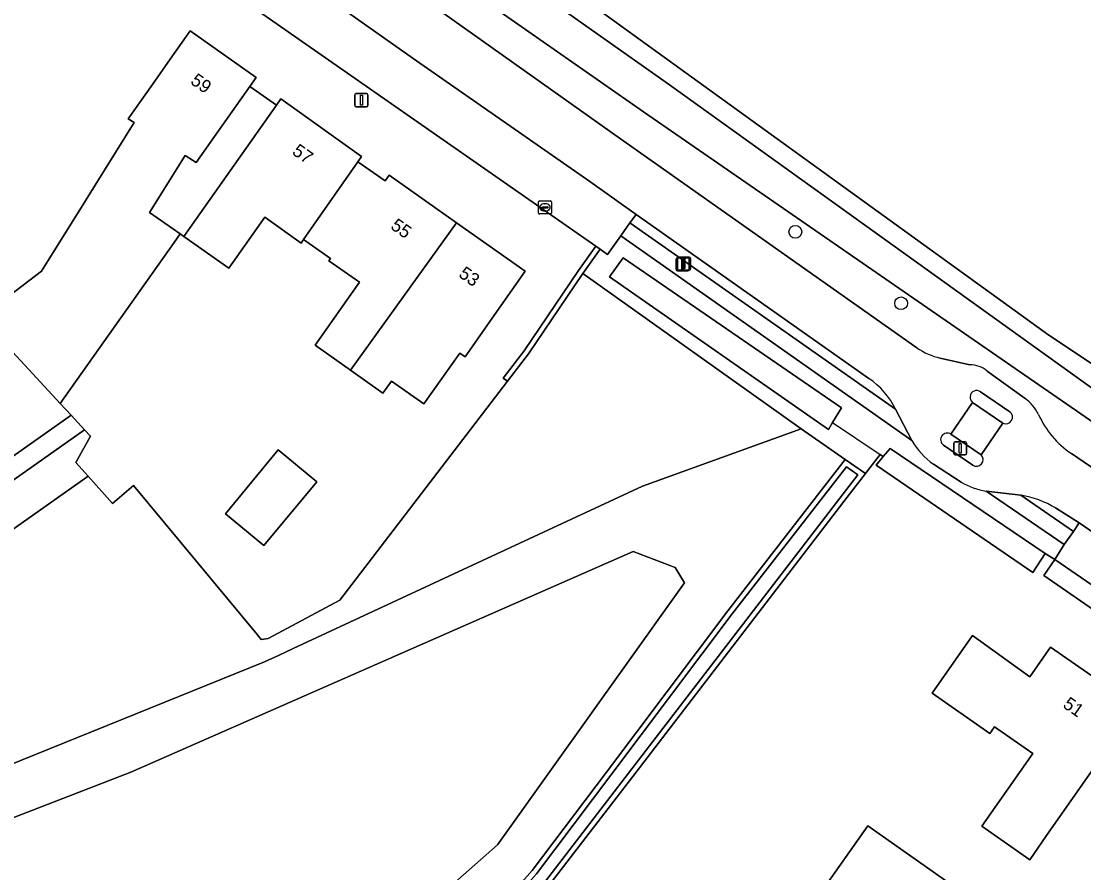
# Model space of a CAD drawing. Extents: x 163859 to 164644, y 379566 to 382155.
# Drawn here: x 164243.8 to 164325.1, y 381742.3 to 381807.4 of the extents above; entities that cross this region are included whole.
import ezdxf

# ---------------------------------------------------------------- set-up
doc = ezdxf.new("R2010")
doc.units = 0
for name, color, linetype in [('IMGEO_Boom', 7, 'Continuous'), ('IMGEO_Duiker', 7, 'Continuous'), ('IMGEO_Erf', 7, 'Continuous'), ('IMGEO_Fietspad_open', 7, 'Continuous'), ('IMGEO_Grasland_agrarisch', 7, 'Continuous'), ('IMGEO_Grasland_overig', 7, 'Continuous'), ('IMGEO_Groenvoorziening', 7, 'Continuous'), ('IMGEO_Haag', 7, 'Continuous'), ('IMGEO_Hek', 7, 'Continuous'), ('IMGEO_Kolk', 7, 'Continuous'), ('IMGEO_Lichtmast', 7, 'Continuous'), ('IMGEO_Loofbos', 7, 'Continuous'), ('IMGEO_Oever', 7, 'Continuous'), ('IMGEO_Pand', 7, 'Continuous'), ('IMGEO_Pand_nummerreeks', 7, 'Continuous'), ('IMGEO_Parkeervlak_open', 7, 'Continuous'), ('IMGEO_Rijbaan_lokaal_gesloten', 7, 'Continuous'), ('IMGEO_Rijbaan_lokaal_open', 7, 'Continuous'), ('IMGEO_Voetpad_onverhard', 7, 'Continuous'), ('IMGEO_Voetpad_open', 7, 'Continuous'), ('IMGEO_Waterloop', 7, 'Continuous')]:
    doc.layers.add(name, color=color, linetype=linetype)

msp = doc.modelspace()

# ---------------------------------------------------------------- linework, layer by layer
at = {"layer": 'IMGEO_Boom'}
for centre in [(164303.037, 381791.326), (164311.134, 381785.861)]:
    msp.add_circle(centre, 0.489, dxfattribs=at)
at = {"layer": 'IMGEO_Duiker'}
msp.add_lwpolyline([(164305.887, 381776.735), (164309.527, 381774.292)], dxfattribs=at)
at = {"layer": 'IMGEO_Erf'}
for points in [[(164232.439, 381822.106), (164231.909, 381821.33), (164235.808, 381818.657), (164230.696, 381811.217), (164225.107, 381816.082), (164225.837, 381817.086), (164221.471, 381820.037), (164221.61, 381820.246), (164220.683, 381820.865), (164219.83, 381819.623), (164212.364, 381823.54), (164205.955, 381814.209), (164235.043, 381794.138), (164235.285, 381793.932), (164235.601, 381793.483), (164234.237, 381791.715), (164240.69, 381784.76), (164245.37, 381788.308), (164248.754, 381793.758), (164252.441, 381799.696), (164251.999, 381799.981), (164253.852, 381802.608)], [(164253.852, 381802.608), (164255.207, 381804.528), (164256.734, 381806.693), (164261.781, 381803.132), (164261.3, 381802.45), (164263.334, 381801.016), (164263.671, 381801.494), (164269.847, 381797.094), (164269.567, 381796.692), (164271.666, 381795.229), (164271.965, 381795.652), (164277.126, 381792.011), (164282.379, 381788.304), (164279.497, 381784.219), (164277.768, 381781.768), (164277.372, 381782.047), (164274.626, 381778.156), (164272.14, 381779.911), (164271.486, 381778.984), (164268.996, 381780.742), (164266.291, 381782.65), (164269.69, 381787.468), (164267.354, 381789.116), (164267.482, 381789.298), (164265.417, 381790.737), (164265.231, 381790.47), (164262.445, 381792.436), (164259.695, 381788.538), (164256.247, 381790.972), (164255.965, 381791.171), (164255.507, 381790.522), (164246.795, 381778.181), (164247.624, 381777.288), (164248.655, 381776.177), (164249.105, 381775.692), (164247.987, 381773.682), (164248.925, 381772.63), (164250.791, 381770.539), (164252.413, 381771.917), (164261.898, 381760.489), (164262.182, 381760.148), (164262.711, 381760.207), (164268.185, 381763.137), (164281.013, 381779.902), (164280.681, 381780.125), (164282.289, 381782.226), (164286.443, 381788.361), (164287.783, 381790.232), (164256.006, 381812.389)], [(164381.892, 381725.724), (164366.579, 381736.251), (164365.238, 381734.407), (164343.09, 381750), (164341.646, 381751.017), (164341.728, 381751.199), (164335.582, 381755.465), (164335.669, 381755.626), (164322.057, 381765.024), (164322.896, 381766.247), (164322.167, 381766.721), (164321.202, 381765.27), (164309.218, 381773.471), (164309.769, 381774.13), (164309.527, 381774.292), (164308.748, 381773.279), (164308.401, 381772.828), (164307.015, 381771.024), (164290.861, 381750), (164280.775, 381736.889), (164280.475, 381736.472), (164297.431, 381715.017), (164336.625, 381665.424)]]:
    msp.add_lwpolyline(points, dxfattribs=at)
for points in [[(164263.476, 381774.646), (164266.428, 381772.203), (164262.385, 381767.319), (164259.434, 381769.762)], [(164320.981, 381743.295), (164317.322, 381745.846), (164321.205, 381751.416), (164318.285, 381753.452), (164317.93, 381752.943), (164313.509, 381756.026), (164316.591, 381760.447), (164320.99, 381757.29), (164322.574, 381759.563), (164329.133, 381754.99), (164325.139, 381749.259), (164322.268, 381745.141)], [(164304.982, 381740.792), (164308.591, 381745.895), (164315.139, 381741.264), (164311.53, 381736.161)]]:
    msp.add_lwpolyline(points, close=True, dxfattribs=at)
at = {"layer": 'IMGEO_Fietspad_open'}
for points in [[(164290.39, 381792.012), (164289.678, 381791.017), (164311.945, 381775.371), (164310.709, 381777.754)], [(164324.32, 381768.391), (164320.292, 381771.18), (164317.646, 381771.484), (164323.62, 381767.407)]]:
    msp.add_lwpolyline(points, close=True, dxfattribs=at)
at = {"layer": 'IMGEO_Grasland_agrarisch'}
msp.add_lwpolyline([(164303.655, 381951.333), (164266.944, 381922.737), (164277.667, 381908.3), (164278.876, 381906.816), (164278.809, 381906.762), (164279.852, 381905.358), (164303.691, 381871.549), (164284.619, 381860.24), (164259.755, 381889.448), (164267.387, 381895.767), (164258.029, 381908.469), (164254.791, 381905.941), (164252.396, 381909.265), (164208.654, 381876.058), (164201.663, 381868.745), (164211.763, 381860.7), (164222.906, 381852.769), (164256.457, 381829.627), (164286.005, 381809.753), (164322.428, 381783.408), (164335.006, 381775.051), (164338.747, 381777.229), (164392.726, 381806.597)], dxfattribs=at)
at = {"layer": 'IMGEO_Grasland_overig'}
msp.add_lwpolyline([(164264.597, 381822.915), (164293.413, 381802.563), (164333.203, 381774.002), (164335.006, 381775.051), (164322.428, 381783.408), (164286.005, 381809.753)], dxfattribs=at)
at = {"layer": 'IMGEO_Groenvoorziening'}
for points in [[(164175.458, 381878.387), (164203.483, 381859.285), (164205.181, 381858.114), (164214.31, 381851.815), (164215.15, 381853.032), (164227.892, 381844.304), (164227.341, 381843.488), (164229.978, 381841.659), (164230.539, 381842.463), (164236.331, 381838.448), (164235.41, 381837.168), (164242.387, 381832.326), (164242.758, 381832.059), (164272.361, 381810.742), (164289.667, 381798.436), (164312.339, 381782.446)], [(164324.169, 381774.363), (164359.822, 381750), (164360.25, 381749.708), (164360.489, 381750.103), (164360.511, 381750.139), (164361.118, 381751.14), (164362.264, 381753.03), (164362.019, 381753.203), (164361.428, 381751.86), (164361.269, 381751.975), (164350.837, 381759.485), (164291.421, 381800.511), (164261.825, 381821.183)], [(164308.664, 381780.116), (164290.856, 381792.662), (164290.39, 381792.012), (164310.709, 381777.754)], [(164311.945, 381775.371), (164289.678, 381791.017), (164288.789, 381789.762), (164288.679, 381789.603), (164288.111, 381790.003), (164286.771, 381788.132), (164303.488, 381776.262), (164306.859, 381773.906), (164308.401, 381772.828), (164308.748, 381773.279), (164309.527, 381774.292), (164309.769, 381774.13), (164310.292, 381774.757), (164322.167, 381766.721), (164322.896, 381766.247), (164323.62, 381767.407), (164317.646, 381771.484)], [(164314.13, 381781.666), (164316.399, 381781.156)], [(164317.71, 381780.678), (164320.628, 381778.579)], [(164319.454, 381777.567), (164317.208, 381779.079)], [(164316.604, 381778.279), (164318.918, 381776.694)], [(164317.251, 381774.26), (164314.948, 381775.851)], [(164314.366, 381775.008), (164316.609, 381773.48)], [(164315.735, 381772.178), (164313.617, 381773.55)], [(164320.292, 381771.18), (164324.32, 381768.391), (164324.768, 381769.068), (164322.955, 381770.199)]]:
    msp.add_lwpolyline(points, dxfattribs=at)
for points in [[(164288.111, 381790.003), (164287.783, 381790.232), (164286.443, 381788.361), (164282.289, 381782.226), (164280.681, 381780.125), (164281.013, 381779.902), (164282.62, 381782.002), (164286.771, 381788.132)], [(164305.887, 381776.735), (164305.568, 381776.211), (164288.824, 381787.871), (164289.86, 381789.347), (164306.567, 381777.852)], [(164210.769, 381745.696), (164248.925, 381772.63), (164247.987, 381773.682), (164249.105, 381775.692), (164248.655, 381776.177), (164208.627, 381747.962)]]:
    msp.add_lwpolyline(points, close=True, dxfattribs=at)
for centre, radius, start, end in [((164315.296, 381786.789), 5.254, 235.7526, 257.1801), ((164316.401, 381779.124), 2.032, 49.88576, 90.0498), ((164305.189, 381775.041), 6.15, 26.17178, 55.59971), ((164316.906, 381778.679), 0.501, 52.9472, 232.9472), ((164318.547, 381775.829), 3.449, 26.20519, 52.88034), ((164319.152, 381777.151), 0.514, 242.85124, 54.05101), ((164328.176, 381780.315), 7.175, 204.39232, 236.05461), ((164314.668, 381775.422), 0.512, 56.8407, 233.91757), ((164317.09, 381778.417), 5.98, 210.6273, 234.48755), ((164316.897, 381773.897), 0.507, 235.41583, 45.67015), ((164318.517, 381776.861), 5.448, 239.2862, 260.79574), ((164319.002, 381763.574), 7.715, 59.17867, 80.3756)]:
    msp.add_arc(centre, radius, start, end, dxfattribs=at)
at = {"layer": 'IMGEO_Haag'}
msp.add_lwpolyline([(164288.111, 381790.003), (164287.783, 381790.232), (164286.443, 381788.361), (164282.289, 381782.226), (164280.681, 381780.125), (164281.013, 381779.902), (164282.62, 381782.002), (164286.771, 381788.132)], close=True, dxfattribs=at)
for points in [[(164319.454, 381777.567), (164317.208, 381779.079)], [(164316.604, 381778.279), (164318.918, 381776.694)], [(164317.251, 381774.26), (164314.948, 381775.851)], [(164314.366, 381775.008), (164316.609, 381773.48)], [(164320.292, 381771.18), (164324.32, 381768.391), (164324.768, 381769.068), (164322.955, 381770.199)]]:
    msp.add_lwpolyline(points, dxfattribs=at)
for centre, radius, start, end in [((164316.906, 381778.679), 0.501, 52.9472, 232.9472), ((164319.152, 381777.151), 0.514, 242.85124, 54.05101), ((164314.668, 381775.422), 0.512, 56.8407, 233.91757), ((164316.897, 381773.897), 0.507, 235.41583, 45.67015), ((164319.002, 381763.574), 7.715, 59.17867, 80.3756)]:
    msp.add_arc(centre, radius, start, end, dxfattribs=at)
at = {"layer": 'IMGEO_Hek'}
msp.add_lwpolyline([(164262.182, 381760.148), (164262.711, 381760.207), (164268.185, 381763.137), (164281.013, 381779.902)], dxfattribs=at)
at = {"layer": 'IMGEO_Kolk'}
for p, q in [((164283.387, 381792.764), (164283.387, 381793.616)), ((164283.462, 381793.69), (164284.314, 381793.69)), ((164284.388, 381793.616), (164284.388, 381792.764)), ((164283.646, 381793.184), (164283.646, 381793.196)), ((164284.084, 381793.147), (164283.686, 381793.147)), ((164283.689, 381793.233), (164284.087, 381793.233)), ((164283.898, 381792.91), (164283.873, 381792.91)), ((164283.875, 381793.47), (164283.9, 381793.47)), ((164284.13, 381793.196), (164284.13, 381793.184)), ((164284.314, 381792.69), (164283.462, 381792.69))]:
    msp.add_line(p, q, dxfattribs=at)
for points in [[(164283.387, 381792.764), (164283.387, 381793.616)], [(164283.462, 381793.69), (164284.314, 381793.69)], [(164284.388, 381793.616), (164284.388, 381792.764)], [(164284.314, 381792.69), (164283.462, 381792.69)]]:
    msp.add_lwpolyline(points, dxfattribs=at)
for centre, radius, start, end in [((164283.464, 381793.614), 0.0765, 91.55205, 178.44795), ((164283.464, 381793.614), 0.0765, 91.55205, 178.44795), ((164284.312, 381793.614), 0.0765, 1.55205, 88.44795), ((164284.312, 381793.614), 0.0765, 1.55205, 88.44795), ((164283.464, 381792.766), 0.0765, 181.55205, 268.44795), ((164283.464, 381792.766), 0.0765, 181.55205, 268.44795), ((164283.686, 381793.193), 0.0403, 85.87752, 175.75265), ((164283.683, 381793.183), 0.0366, 178.93798, 274.71019), ((164284.087, 381793.19), 0.043, 264.86636, 352.45326), ((164284.091, 381793.195), 0.0386, 1.73085, 96.63898), ((164284.312, 381792.766), 0.0765, 271.55205, 358.44795), ((164284.312, 381792.766), 0.0765, 271.55205, 358.44795)]:
    msp.add_arc(centre, radius, start, end, dxfattribs=at)
for centre, major_axis, ratio, start_param, end_param in [((164283.874, 381793.19), (-0.387, 0.002), 0.722429, 4.712389, 7.853982), ((164283.899, 381793.19), (-0.39, 0.002), 0.717154, 1.570796, 4.712389)]:
    msp.add_ellipse(centre, major_axis=major_axis, ratio=ratio, start_param=start_param, end_param=end_param, dxfattribs=at)
at = {"layer": 'IMGEO_Lichtmast'}
for p, q in [((164269.345, 381800.996), (164269.345, 381801.796)), ((164269.345, 381801.796), (164269.345, 381800.996)), ((164269.445, 381801.896), (164270.235, 381801.896)), ((164270.235, 381801.896), (164269.445, 381801.896)), ((164270.335, 381801.796), (164270.335, 381800.996)), ((164270.335, 381800.996), (164270.335, 381801.796)), ((164270.235, 381800.896), (164269.445, 381800.896)), ((164269.445, 381800.896), (164270.235, 381800.896)), ((164293.926, 381788.444), (164293.926, 381789.244)), ((164293.926, 381789.244), (164293.926, 381788.444)), ((164294.026, 381789.344), (164294.816, 381789.344)), ((164294.816, 381789.344), (164294.026, 381789.344)), ((164294.026, 381788.493), (164294.026, 381789.293)), ((164294.026, 381789.293), (164294.026, 381788.493)), ((164294.126, 381789.393), (164294.916, 381789.393)), ((164294.916, 381789.393), (164294.126, 381789.393)), ((164294.916, 381789.244), (164294.916, 381788.444)), ((164294.916, 381788.444), (164294.916, 381789.244)), ((164295.016, 381789.293), (164295.016, 381788.493)), ((164295.016, 381788.493), (164295.016, 381789.293)), ((164294.816, 381788.344), (164294.026, 381788.344)), ((164294.026, 381788.344), (164294.816, 381788.344)), ((164294.916, 381788.393), (164294.126, 381788.393)), ((164294.126, 381788.393), (164294.916, 381788.393)), ((164315.157, 381774.358), (164315.157, 381775.158)), ((164315.157, 381775.158), (164315.157, 381774.358)), ((164315.257, 381775.258), (164316.047, 381775.258)), ((164316.047, 381775.258), (164315.257, 381775.258)), ((164316.147, 381775.158), (164316.147, 381774.358)), ((164316.147, 381774.358), (164316.147, 381775.158)), ((164316.047, 381774.258), (164315.257, 381774.258)), ((164315.257, 381774.258), (164316.047, 381774.258))]:
    msp.add_line(p, q, dxfattribs=at)
for points in [[(164269.765, 381801.771), (164269.915, 381801.771), (164269.915, 381801.021), (164269.765, 381801.021), (164269.765, 381801.771)], [(164294.346, 381789.219), (164294.496, 381789.219), (164294.496, 381788.469), (164294.346, 381788.469), (164294.346, 381789.219)], [(164294.446, 381789.268), (164294.596, 381789.268), (164294.596, 381788.518), (164294.446, 381788.518), (164294.446, 381789.268)], [(164315.577, 381775.133), (164315.727, 381775.133), (164315.727, 381774.383), (164315.577, 381774.383), (164315.577, 381775.133)]]:
    msp.add_lwpolyline(points, dxfattribs=at)
for centre, start, end in [((164269.445, 381801.796), 90, 180), ((164269.445, 381801.796), 90, 180), ((164270.235, 381801.796), 0, 90), ((164270.235, 381801.796), 360, 90), ((164269.445, 381800.996), 180, 270), ((164269.445, 381800.996), 180, 270), ((164270.235, 381800.996), 270, 0), ((164270.235, 381800.996), 270, 0), ((164294.026, 381789.244), 90, 180), ((164294.026, 381789.244), 90, 180), ((164294.126, 381789.293), 90, 180), ((164294.126, 381789.293), 90, 180), ((164294.816, 381789.244), 0, 90), ((164294.816, 381789.244), 360, 90), ((164294.916, 381789.293), 0, 90), ((164294.916, 381789.293), 360, 90), ((164294.026, 381788.444), 180, 270), ((164294.026, 381788.444), 180, 270), ((164294.126, 381788.493), 180, 270), ((164294.126, 381788.493), 180, 270), ((164294.816, 381788.444), 270, 0), ((164294.816, 381788.444), 270, 0), ((164294.916, 381788.493), 270, 0), ((164294.916, 381788.493), 270, 0), ((164315.257, 381775.158), 90, 180), ((164315.257, 381775.158), 90, 180), ((164316.047, 381775.158), 0, 90), ((164316.047, 381775.158), 360, 90), ((164315.257, 381774.358), 180, 270), ((164315.257, 381774.358), 180, 270), ((164316.047, 381774.358), 270, 0), ((164316.047, 381774.358), 270, 0)]:
    msp.add_arc(centre, 0.1, start, end, dxfattribs=at)
at = {"layer": 'IMGEO_Loofbos'}
for points in [[(164200.236, 381756.837), (164207.613, 381749.034), (164247.624, 381777.288), (164246.795, 381778.181), (164240.69, 381784.76), (164234.237, 381791.715), (164194.821, 381764.538), (164195.578, 381763.752), (164196.361, 381762.278)], [(164241.546, 381750), (164262.438, 381758.432), (164263.501, 381758.926), (164264.622, 381759.446), (164291.345, 381771.857), (164303.488, 381776.262), (164286.771, 381788.132), (164282.62, 381782.002), (164281.013, 381779.902), (164268.185, 381763.137), (164262.711, 381760.207), (164262.182, 381760.148), (164261.898, 381760.489), (164252.413, 381771.917), (164250.791, 381770.539), (164248.925, 381772.63), (164210.769, 381745.696)]]:
    msp.add_lwpolyline(points, dxfattribs=at)
msp.add_lwpolyline([(164244.52, 381712.921), (164280.261, 381744.42), (164294.549, 381764.484), (164293.858, 381765.634), (164290.621, 381766.859), (164252.196, 381750), (164227.202, 381740.325), (164222.033, 381737.719)], close=True, dxfattribs=at)
at = {"layer": 'IMGEO_Oever'}
for points in [[(164279.12, 381735.741), (164283.656, 381730.803), (164296.619, 381714.323), (164297.331, 381714.931), (164297.431, 381715.017), (164280.475, 381736.472), (164280.775, 381736.889), (164290.861, 381750), (164307.015, 381771.024), (164308.401, 381772.828), (164306.859, 381773.906), (164297.874, 381762.34), (164288.585, 381750), (164282.911, 381742.463), (164278.67, 381737.671), (164248.006, 381711.607), (164248.436, 381711.091), (164248.866, 381710.575)], [(164280.126, 381736.689), (164280.149, 381736.16), (164297.146, 381715.024), (164296.608, 381714.604), (164296.141, 381715.203), (164283.995, 381730.764), (164279.309, 381736.013), (164279.022, 381736.193), (164248.919, 381711.152), (164248.751, 381711.353), (164248.581, 381711.558), (164278.958, 381737.378), (164283.229, 381742.203), (164288.913, 381749.753), (164298.2, 381762.091), (164306.944, 381773.347), (164307.815, 381772.738), (164306.69, 381771.274), (164290.536, 381750.25), (164280.446, 381737.134)]]:
    msp.add_lwpolyline(points, close=True, dxfattribs=at)
at = {"layer": 'IMGEO_Pand'}
for points in [[(164256.345, 381797.177), (164257.193, 381796.63), (164258.899, 381799.047), (164261.3, 381802.45), (164261.781, 381803.132), (164256.734, 381806.693), (164255.207, 381804.528), (164253.852, 381802.608), (164251.999, 381799.981), (164252.441, 381799.696), (164248.754, 381793.758), (164245.37, 381788.308), (164240.69, 381784.76), (164246.795, 381778.181), (164255.507, 381790.522), (164255.965, 381791.171), (164253.636, 381792.815)], [(164263.334, 381801.016), (164261.3, 381802.45), (164258.899, 381799.047), (164257.193, 381796.63), (164256.345, 381797.177), (164253.636, 381792.815), (164255.965, 381791.171), (164256.247, 381790.972)], [(164269.567, 381796.692), (164269.847, 381797.094), (164263.671, 381801.494), (164263.334, 381801.016), (164256.247, 381790.972), (164259.695, 381788.538), (164262.445, 381792.436), (164265.231, 381790.47), (164265.417, 381790.737)], [(164277.126, 381792.011), (164271.965, 381795.652), (164271.666, 381795.229), (164269.567, 381796.692), (164265.417, 381790.737), (164267.482, 381789.298), (164267.354, 381789.116), (164269.69, 381787.468), (164266.291, 381782.65), (164268.996, 381780.742)], [(164282.379, 381788.304), (164277.126, 381792.011), (164268.996, 381780.742), (164271.486, 381778.984), (164272.14, 381779.911), (164274.626, 381778.156), (164277.372, 381782.047), (164277.768, 381781.768), (164279.497, 381784.219)], [(164259.434, 381769.762), (164262.385, 381767.319), (164266.428, 381772.203), (164263.476, 381774.646)], [(164322.268, 381745.141), (164325.139, 381749.259), (164329.133, 381754.99), (164322.574, 381759.563), (164320.99, 381757.29), (164316.591, 381760.447), (164313.509, 381756.026), (164317.93, 381752.943), (164318.285, 381753.452), (164321.205, 381751.416), (164317.322, 381745.846), (164320.981, 381743.295)], [(164311.53, 381736.161), (164315.139, 381741.264), (164308.591, 381745.895), (164304.982, 381740.792)]]:
    msp.add_lwpolyline(points, close=True, dxfattribs=at)
at = {"layer": 'IMGEO_Parkeervlak_open'}
for points in [[(164274.046, 381804.404), (164268.514, 381808.317), (164257.966, 381815.614), (164257.217, 381814.474), (164256.552, 381813.463), (164256.006, 381812.389), (164287.783, 381790.232), (164288.111, 381790.003), (164288.679, 381789.603), (164288.789, 381789.762), (164289.678, 381791.017), (164290.39, 381792.012), (164290.856, 381792.662), (164287.307, 381795.184)], [(164352.536, 381750), (164324.768, 381769.068), (164324.32, 381768.391), (164323.62, 381767.407), (164322.896, 381766.247), (164346.556, 381750), (164366.579, 381736.251), (164381.892, 381725.724), (164406.418, 381708.86), (164407.122, 381709.878), (164407.816, 381710.901), (164408.346, 381711.663), (164383.72, 381728.586)]]:
    msp.add_lwpolyline(points, close=True, dxfattribs=at)
at = {"layer": 'IMGEO_Rijbaan_lokaal_gesloten'}
for points in [[(164289.667, 381798.436), (164272.361, 381810.742), (164242.758, 381832.059), (164239.966, 381828.066), (164257.966, 381815.614), (164268.514, 381808.317), (164274.046, 381804.404), (164287.307, 381795.184), (164290.856, 381792.662), (164308.664, 381780.116)], [(164312.339, 381782.446), (164289.667, 381798.436)], [(164316.399, 381781.156), (164314.13, 381781.666)], [(164320.628, 381778.579), (164317.71, 381780.678)], [(164317.208, 381779.079), (164319.454, 381777.567)], [(164314.948, 381775.851), (164316.604, 381778.279)], [(164310.709, 381777.754), (164311.945, 381775.371)], [(164318.918, 381776.694), (164317.251, 381774.26)], [(164316.609, 381773.48), (164314.366, 381775.008)], [(164322.955, 381770.199), (164324.768, 381769.068), (164352.536, 381750), (164383.72, 381728.586), (164408.346, 381711.663), (164410.608, 381714.952), (164385.909, 381731.949), (164382.848, 381734.057), (164381.018, 381735.317), (164360.792, 381749.337), (164360.25, 381749.708), (164359.822, 381750), (164324.169, 381774.363)], [(164313.617, 381773.55), (164315.735, 381772.178)], [(164317.646, 381771.484), (164320.292, 381771.18)]]:
    msp.add_lwpolyline(points, dxfattribs=at)
for centre, radius, start, end in [((164315.296, 381786.789), 5.254, 235.7526, 257.1801), ((164316.401, 381779.124), 2.032, 49.88576, 90.0498), ((164305.189, 381775.041), 6.15, 26.17178, 55.59971), ((164316.906, 381778.679), 0.501, 52.9472, 232.9472), ((164318.547, 381775.829), 3.449, 26.20519, 52.88034), ((164319.152, 381777.151), 0.514, 242.85124, 54.05101), ((164328.176, 381780.315), 7.175, 204.39232, 236.05461), ((164314.668, 381775.422), 0.512, 56.8407, 233.91757), ((164317.09, 381778.417), 5.98, 210.6273, 234.48755), ((164316.897, 381773.897), 0.507, 235.41583, 45.67015), ((164318.517, 381776.861), 5.448, 239.2862, 260.79574), ((164319.002, 381763.574), 7.715, 59.17867, 80.3756)]:
    msp.add_arc(centre, radius, start, end, dxfattribs=at)
at = {"layer": 'IMGEO_Rijbaan_lokaal_open'}
msp.add_lwpolyline([(164317.251, 381774.26), (164318.918, 381776.694), (164316.604, 381778.279), (164314.948, 381775.851)], close=True, dxfattribs=at)
at = {"layer": 'IMGEO_Voetpad_onverhard'}
msp.add_lwpolyline([(164219.942, 381735.849), (164244.369, 381708.516), (164246.315, 381710.17), (164248.006, 381711.607), (164278.67, 381737.671), (164282.911, 381742.463), (164288.585, 381750), (164297.874, 381762.34), (164306.859, 381773.906), (164303.488, 381776.262), (164291.345, 381771.857), (164264.622, 381759.446), (164263.501, 381758.926), (164262.438, 381758.432), (164241.546, 381750)], dxfattribs=at)
msp.add_lwpolyline([(164244.52, 381712.921), (164222.033, 381737.719), (164227.202, 381740.325), (164252.196, 381750), (164290.621, 381766.859), (164293.858, 381765.634), (164294.549, 381764.484), (164280.261, 381744.42)], close=True, dxfattribs=at)
at = {"layer": 'IMGEO_Voetpad_open'}
for points in [[(164310.292, 381774.757), (164309.769, 381774.13), (164309.218, 381773.471), (164321.202, 381765.27), (164322.167, 381766.721)], [(164322.896, 381766.247), (164322.057, 381765.024), (164335.669, 381755.626), (164335.582, 381755.465), (164341.728, 381751.199), (164341.646, 381751.017), (164343.09, 381750), (164365.238, 381734.407), (164366.579, 381736.251), (164346.556, 381750)]]:
    msp.add_lwpolyline(points, close=True, dxfattribs=at)
at = {"layer": 'IMGEO_Waterloop'}
for points in [[(164293.413, 381802.563), (164264.597, 381822.915), (164263.512, 381823.639), (164244.45, 381836.352), (164223.061, 381850.617), (164221.968, 381849.023), (164261.825, 381821.183), (164291.421, 381800.511), (164350.837, 381759.485), (164361.269, 381751.975), (164361.428, 381751.86), (164362.019, 381753.203), (164361.552, 381753.543), (164351.545, 381760.837), (164333.203, 381774.002)], [(164306.567, 381777.852), (164289.86, 381789.347), (164288.824, 381787.871), (164305.568, 381776.211), (164305.887, 381776.735)], [(164207.613, 381749.034), (164208.627, 381747.962), (164248.655, 381776.177), (164247.624, 381777.288)], [(164280.126, 381736.689), (164280.446, 381737.134), (164290.536, 381750.25), (164306.69, 381771.274), (164307.815, 381772.738), (164306.944, 381773.347), (164298.2, 381762.091), (164288.913, 381749.753), (164283.229, 381742.203), (164278.958, 381737.378), (164248.581, 381711.558), (164248.751, 381711.353), (164248.919, 381711.152), (164279.022, 381736.193), (164279.309, 381736.013), (164283.995, 381730.764), (164296.141, 381715.203), (164296.608, 381714.604), (164297.146, 381715.024), (164280.149, 381736.16)]]:
    msp.add_lwpolyline(points, close=True, dxfattribs=at)

# ---------------------------------------------------------------- texts
at = {"layer": 'IMGEO_Pand_nummerreeks'}
for s, rotation, p in [('59', 324.79174, (164256.692, 381802.709)), ('57', 324.79174, (164264.472, 381797.311)), ('55', 324.79174, (164272.003, 381791.611)), ('53', 324.79174, (164277.21, 381787.937)), ('51', 325.13444, (164323.439, 381754.995))]:
    msp.add_text(s, height=1, rotation=rotation, dxfattribs=at).set_placement(p)

doc.saveas('drawing.dxf')
